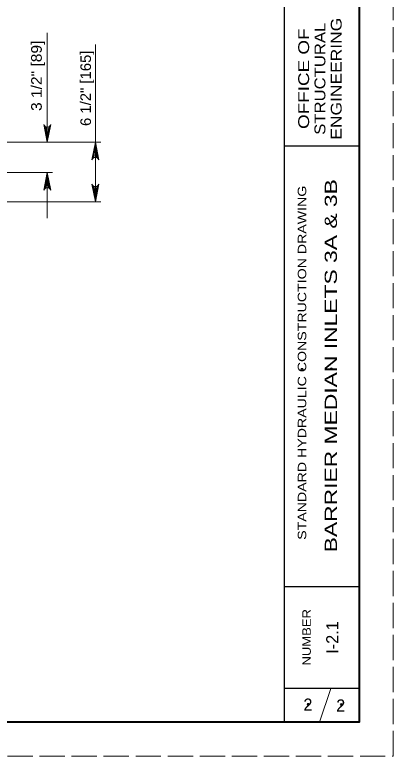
# Model space of a CAD drawing. Extents: x 1083.1 to 1123, y 697.4 to 741.4.
# Drawn here: x 1111.55 to 1117.13, y 697.35 to 708.29 of the extents above; entities that cross this region are included whole.
import ezdxf
from ezdxf.enums import TextEntityAlignment as Align

# ---------------------------------------------------------------- set-up
doc = ezdxf.new("R2010")
doc.units = 0
doc.header["$LTSCALE"] = 0.062
doc.header["$PDMODE"] = 32
doc.header["$PDSIZE"] = 0.031
doc.linetypes.add('LONG_DASHED', pattern=[7.5, 6, -1.5])
doc.layers.add('1', color=7, linetype='Continuous', lineweight=13)

msp = doc.modelspace()

# ---------------------------------------------------------------- linework, layer by layer
at = {"layer": '1', "lineweight": 25}
for p, q in [((1115.52642, 697.85408), (1115.52642, 718.85408)), ((1116.62642, 718.85408), (1116.62642, 697.85408)), ((1116.62642, 706.35408), (1115.52642, 706.35408)), ((1116.62642, 699.85408), (1115.52642, 699.85408)), ((1116.62642, 698.35408), (1115.52642, 698.35408))]:
    msp.add_line(p, q, dxfattribs=at)
at = {"layer": '1'}
for p, q in [((1112.03225, 708.02383), (1112.03225, 706.41158)), ((1112.74025, 707.8525), (1112.74025, 705.53383)), ((1111.99942, 706.64617), (1112.03225, 706.41158)), ((1112.0685, 706.64892), (1112.03225, 706.41158)), ((1112.01567, 706.63825), (1112.03225, 706.41158)), ((1112.05333, 706.64), (1112.03225, 706.41158)), ((1112.03225, 706.63583), (1112.03225, 706.41158)), ((1110.3815, 706.41158), (1112.81892, 706.41158)), ((1112.704, 706.17417), (1112.74025, 706.41158)), ((1112.71917, 706.18317), (1112.74025, 706.41158)), ((1112.74025, 706.18733), (1112.74025, 706.41158)), ((1112.75683, 706.18492), (1112.74025, 706.41158)), ((1112.77308, 706.17692), (1112.74025, 706.41158)), ((1111.996, 705.72567), (1112.03225, 705.96308)), ((1112.01117, 705.73467), (1112.03225, 705.96308)), ((1112.03225, 705.73883), (1112.03225, 705.96308)), ((1112.04883, 705.73642), (1112.03225, 705.96308)), ((1112.06508, 705.7285), (1112.03225, 705.96308)), ((1112.03225, 705.96308), (1112.03225, 705.29242)), ((1112.70742, 705.7685), (1112.74025, 705.53383)), ((1112.7765, 705.77125), (1112.74025, 705.53383)), ((1112.72367, 705.7605), (1112.74025, 705.53383)), ((1112.76133, 705.76225), (1112.74025, 705.53383)), ((1112.74025, 705.75808), (1112.74025, 705.53383)), ((1112.81892, 705.53383), (1110.68208, 705.53383)), ((1112.20442, 705.53383), (1112.20442, 705.53217)), ((1116.04308, 697.85408), (1116.20975, 698.35408))]:
    msp.add_line(p, q, dxfattribs=at)
at = {"layer": '1', "linetype": 'LONG_DASHED'}
msp.add_lwpolyline([(1083.12642, 697.35408), (1117.12642, 697.35408), (1117.12642, 719.35408), (1083.12642, 719.35408)], close=True, dxfattribs=at)
at = {"layer": '1', "lineweight": 25}
msp.add_lwpolyline([(1116.62642, 697.85408), (1085.12642, 697.85408), (1085.12642, 718.85408)], dxfattribs=at)
at = {"layer": '1', "lineweight": 40}
msp.add_lwpolyline([(1085.12642, 718.85408), (1116.62642, 718.85408), (1116.62642, 697.85408), (1085.12642, 697.85408)], close=True, dxfattribs=at)
at = {"layer": '1'}
for points in [[(1112.08408, 706.67075), (1112.03225, 706.41158), (1111.98042, 706.67075)], [(1112.68842, 706.15242), (1112.74025, 706.41158), (1112.79208, 706.15242)], [(1112.11092, 705.96308), (1110.81225, 705.96308), (1110.3815, 705.96308)], [(1111.98042, 705.70392), (1112.03225, 705.96308), (1112.08408, 705.70392)], [(1112.79208, 705.793), (1112.74025, 705.53383), (1112.68842, 705.793)]]:
    msp.add_lwpolyline(points, dxfattribs=at)
for centre, start, end in [((1112.03219, 706.69164), 202.08782, 337.91395), ((1112.7403, 706.13149), 22.08782, 157.91395), ((1112.74019, 705.81393), 202.08782, 337.91395), ((1112.0323, 705.68301), 22.08782, 157.91395)]:
    msp.add_arc(centre, 0.05593, start, end, dxfattribs=at)
for p in [(1115.78383, 703.06008), (1116.21667, 703.06742), (1115.8745, 698.11783), (1116.36292, 698.11683)]:
    msp.add_point(p, dxfattribs=at)

# ---------------------------------------------------------------- texts
for s, height, width, p in [('ENGINEERING', 0.16, 1.2, (1116.36817, 707.34862)), ('OFFICE OF', 0.16, 1.3, (1115.88817, 707.34854)), ('STRUCTURAL', 0.16, 1.15, (1116.12817, 707.34854)), ('3 1/2" [89]', 0.156, 1.1, (1111.95067, 707.39137)), ('6 1/2" [165]', 0.156, 1.05, (1112.67542, 707.20758)), ('BARRIER MEDIAN INLETS 3A & 3B', 0.18, 1.4, (1116.29842, 703.11421)), ('STANDARD HYDRAULIC CONSTRUCTION DRAWING', 0.125, 1.25, (1115.84633, 703.15812)), ('NUMBER', 0.125, 1.15, (1115.91342, 699.10817))]:
    msp.add_text(s, height=height, rotation=90, dxfattribs=dict(at, width=width)).set_placement(p, align=Align.CENTER)
msp.add_text('I-2.1', height=0.18, rotation=90, dxfattribs=at).set_placement((1116.32058, 699.10442), align=Align.CENTER)
for p in [(1115.87088, 698.02417), (1116.35371, 698.01158)]:
    msp.add_text('2', height=0.18, dxfattribs=at).set_placement(p, align=Align.CENTER)

doc.saveas('drawing.dxf')
